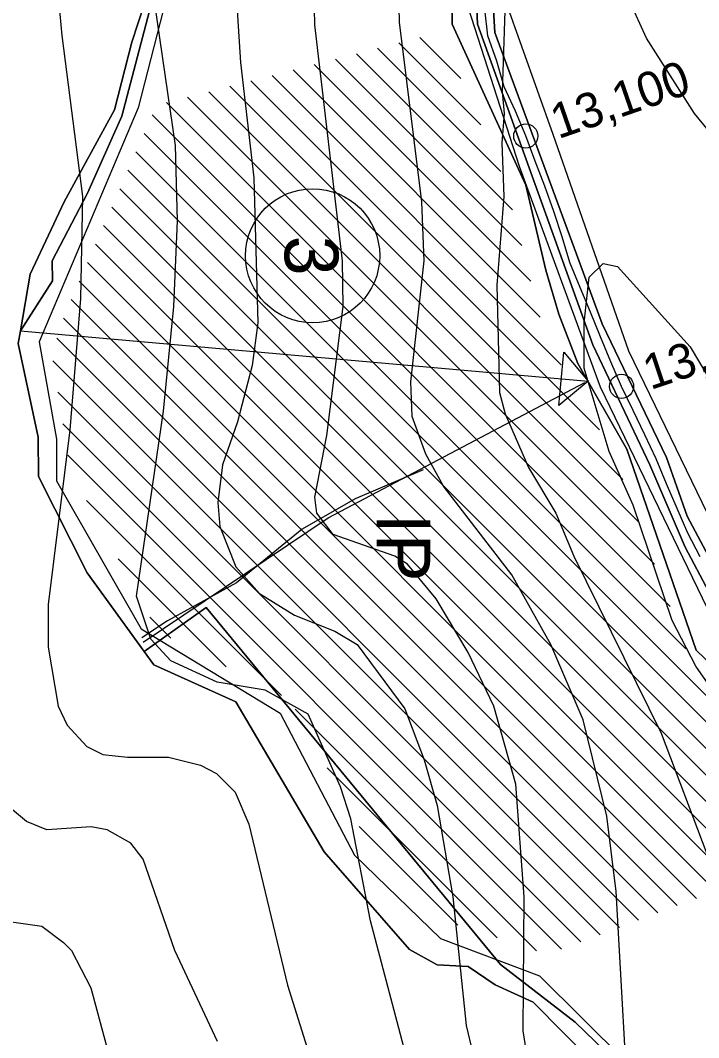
# Model space of a CAD drawing. Extents: x -510989 to -501240, y -1184665 to -1176089.
# Drawn here: x -510240.4 to -509987.5, y -1178334.5 to -1177955.3 of the extents above; entities that cross this region are included whole.
import ezdxf

# ---------------------------------------------------------------- set-up
doc = ezdxf.new("R2010")
doc.units = 0
for name, color, linetype in [('lesni_pozemek', 7, 'Continuous'), ('NAVRH_interakcni_prvky', 7, 'Continuous'), ('NAVRH_revitalizace_toku', 7, 'Continuous'), ('orna_puda', 7, 'Continuous'), ('ostatni_plocha_x_neplodna_puda', 7, 'Continuous'), ('STAV_erozne_ohrozene_plochy', 7, 'Continuous'), ('STAV_odtokove_linie', 7, 'Continuous'), ('STAV_systematicke_odvodneni', 7, 'Continuous'), ('STAV_vyrazne_udolnice', 7, 'Continuous'), ('trasovani_toku', 7, 'Continuous'), ('trvaly_travni_porost', 7, 'Continuous'), ('vodni_plocha_x_vodni_tok_v_koryte_umelem', 7, 'Continuous'), ('vrstevnice_01', 7, 'Continuous'), ('vrstevnice_02', 7, 'Continuous')]:
    doc.layers.add(name, color=color, linetype=linetype)

msp = doc.modelspace()

# ---------------------------------------------------------------- linework, layer by layer
at = {"layer": 'lesni_pozemek'}
msp.add_lwpolyline([(-510189.41, -1177934.52), (-510198.81, -1177963.46), (-510205.37, -1177988.67), (-510224.04, -1178022.91), (-510236.77, -1178049.95), (-510240.38, -1178070.99), (-510241.2, -1178075.75), (-510233.74, -1178110.71), (-510233.66, -1178125.3), (-510215.51, -1178161.2), (-510194.26, -1178190.6), (-510190.68, -1178195.56), (-510160.13, -1178209.33), (-510127.15, -1178265.25), (-510095.33, -1178301.71), (-510084.96, -1178307.4), (-510073.4, -1178308.05), (-510063.41, -1178314.85), (-510049.21, -1178321.31), (-509991.93, -1178379.18)], dxfattribs=at)
msp.add_lwpolyline([(-510187.83, -1177934.64), (-510202.64, -1177991), (-510215.39, -1178019.77), (-510228.62, -1178044.97), (-510228.47, -1178052.46), (-510240.38, -1178070.99), (-510236.77, -1178049.95), (-510224.04, -1178022.91), (-510205.37, -1177988.67), (-510198.81, -1177963.46), (-510189.41, -1177934.52)], close=True, dxfattribs=at)
at = {"layer": 'NAVRH_interakcni_prvky'}
msp.add_lwpolyline([(-510194.66, -1178187.09), (-510125.7, -1178140.77), (-510029.97, -1178090.33)], dxfattribs=at)
at = {"layer": 'NAVRH_revitalizace_toku'}
for points in [[(-510060.1, -1177738.31), (-510046.04, -1177776.27), (-510042.52, -1177800.88), (-510055.18, -1177879.61), (-510059.4, -1177948.51), (-510041.82, -1177997.72), (-510013.7, -1178078.56), (-509968.71, -1178171.36), (-509924.51, -1178222.53), (-509906.94, -1178282.99), (-509903.42, -1178334.31), (-509883.74, -1178387.03), (-509875.3, -1178456.63), (-509874.6, -1178556.46), (-509867.57, -1178669.64)], [(-510079.08, -1177742.53), (-510057.99, -1177785.41), (-510068.53, -1177883.83), (-510073.46, -1177950.62), (-510054.47, -1178009.67), (-510024.24, -1178091.92), (-509980.66, -1178181.91), (-509942.44, -1178221.73), (-509934.15, -1178235.7), (-509920.62, -1178289.39), (-509918.19, -1178331.5), (-509899.91, -1178389.14), (-509890.77, -1178450.3), (-509893.58, -1178526.93), (-509883.74, -1178663.31)]]:
    msp.add_lwpolyline(points, dxfattribs=at)
at = {"layer": 'orna_puda'}
for points in [[(-509986.97, -1177924.63), (-509979.84, -1177959.29), (-509966.64, -1177993.07), (-509958.61, -1178002.56), (-509963.49, -1178019.89), (-509961.34, -1178043.79), (-509958.27, -1178057.57), (-509958.72, -1178072.96), (-509956.26, -1178083.05), (-509933.53, -1178115.39), (-509937.22, -1178120.9), (-509928.78, -1178129.88), (-509922.63, -1178142.75), (-509917.55, -1178147.87), (-509909, -1178165.53), (-509959.6, -1178191.33), (-509969.79, -1178181.42), (-509991.77, -1178140.09), (-509999.48, -1178118.28), (-510023.49, -1178068.48), (-510063.48, -1177959.85), (-510065.05, -1177932.43)], [(-509992.84, -1178367.99), (-510033.53, -1178328.73), (-510061.37, -1178307.23), (-510171.11, -1178174.19), (-510194.26, -1178190.6), (-510215.51, -1178161.2), (-510233.66, -1178125.3), (-510233.74, -1178110.71), (-510241.2, -1178075.75), (-510240.38, -1178070.99), (-510228.47, -1178052.46), (-510228.62, -1178044.97), (-510215.39, -1178019.77), (-510202.64, -1177991), (-510187.83, -1177934.64)], [(-510079.43, -1177947.66), (-510079.36, -1177956.75), (-510051.92, -1178016.68), (-510044.45, -1178048.48), (-510039.57, -1178064.82), (-510032.5, -1178083.21), (-510014.22, -1178115.18), (-509988.47, -1178190.06), (-509953.04, -1178224.13), (-509933.91, -1178266.31), (-509920.86, -1178355.55)]]:
    msp.add_lwpolyline(points, dxfattribs=at)
at = {"layer": 'ostatni_plocha_x_neplodna_puda'}
msp.add_lwpolyline([(-510171.11, -1178174.19), (-510061.37, -1178307.23), (-510033.53, -1178328.73), (-509992.84, -1178367.99), (-509974.29, -1178382.32), (-509974.41, -1178391.9), (-509986.69, -1178390.43), (-509991.93, -1178379.18), (-510049.21, -1178321.31), (-510063.41, -1178314.85), (-510073.4, -1178308.05), (-510084.96, -1178307.4), (-510095.33, -1178301.71), (-510127.15, -1178265.25), (-510160.13, -1178209.33), (-510190.68, -1178195.56), (-510194.26, -1178190.6)], close=True, dxfattribs=at)
at = {"layer": 'STAV_erozne_ohrozene_plochy'}
for p, q in [((-510091.47, -1177961.65), (-510076.17, -1177976.95)), ((-510107.22, -1177965.7), (-510061.31, -1178011.61)), ((-510099.35, -1177963.67), (-510068.74, -1177994.28)), ((-510122.96, -1177969.75), (-510053.48, -1178039.24)), ((-510115.09, -1177967.73), (-510056.9, -1178025.92)), ((-510138.71, -1177973.81), (-510046.63, -1178065.89)), ((-510130.84, -1177971.78), (-510050.05, -1178052.57)), ((-510154.45, -1177977.86), (-510024.43, -1178107.89)), ((-510146.58, -1177975.84), (-510038.72, -1178083.7)), ((-510170.2, -1177981.92), (-510009.89, -1178142.23)), ((-510162.33, -1177979.89), (-510015.77, -1178126.45)), ((-510185.94, -1177985.97), (-509998.13, -1178173.79)), ((-510178.07, -1177983.94), (-510004.01, -1178158.01)), ((-510191.28, -1177990.53), (-509992.25, -1178189.57)), ((-510194.3, -1177997.42), (-509952.67, -1178239.04)), ((-510197.31, -1178004.3), (-509941.41, -1178260.2)), ((-510200.33, -1178011.18), (-509945.17, -1178266.34)), ((-510203.35, -1178018.06), (-509952.36, -1178269.05)), ((-510206.37, -1178024.95), (-509959.55, -1178271.76)), ((-510209.38, -1178031.83), (-509966.74, -1178274.47)), ((-510212.4, -1178038.71), (-509973.93, -1178277.18)), ((-510215.42, -1178045.59), (-509981.12, -1178279.89)), ((-510218.43, -1178052.48), (-509988.31, -1178282.6)), ((-510221.45, -1178059.36), (-509995.5, -1178285.31)), ((-510224.35, -1178066.36), (-510002.69, -1178288.02)), ((-510226.77, -1178073.83), (-510009.88, -1178290.73)), ((-510228.3, -1178082.21), (-510017.07, -1178293.44)), ((-510226.45, -1178093.95), (-510024.26, -1178296.14)), ((-510224.6, -1178105.7), (-510031.45, -1178298.85)), ((-510222.75, -1178117.45), (-510038.64, -1178301.56)), ((-510215.75, -1178134.35), (-510143.07, -1178207.03)), ((-510203.95, -1178156.05), (-510163.7, -1178196.3)), ((-510192.15, -1178177.76), (-510184.33, -1178185.57)), ((-510138.01, -1178212.1), (-510047.94, -1178302.16)), ((-510126.02, -1178233.98), (-510062.63, -1178297.38)), ((-510114.03, -1178255.87), (-510077.32, -1178292.59))]:
    msp.add_line(p, q, dxfattribs=at)
at = {"layer": 'STAV_odtokove_linie'}
msp.add_line((-510240.38, -1178070.99), (-510028.74, -1178089.79), dxfattribs=at)
msp.add_lwpolyline([(-510037.81, -1178078.94), (-510028.74, -1178089.79), (-510039.59, -1178098.86)], close=True, dxfattribs=at)
msp.add_circle((-510131.43, -1178043.05), 25, dxfattribs=at)
at = {"layer": 'STAV_systematicke_odvodneni'}
for p, q in [((-510184.72, -1177941.97), (-510196.48, -1177987.96)), ((-510196.48, -1177987.96), (-510233.36, -1178075.12)), ((-510233.36, -1178075.12), (-510226.95, -1178111.48)), ((-510226.95, -1178111.48), (-510226.95, -1178126.99)), ((-510226.95, -1178126.99), (-510195.41, -1178182.07)), ((-510195.41, -1178182.07), (-510143.56, -1178213.62)), ((-510143.56, -1178213.62), (-510115.77, -1178266.56)), ((-510115.77, -1178266.56), (-510083.7, -1178297.58)), ((-510083.7, -1178297.58), (-510046.81, -1178311.48)), ((-510046.81, -1178311.48), (-509988.02, -1178369.77))]:
    msp.add_line(p, q, dxfattribs=at)
at = {"layer": 'STAV_vyrazne_udolnice'}
msp.add_lwpolyline([(-510090.27, -1178122.86), (-510115.59, -1178133.7), (-510135.29, -1178144.95), (-510159.8, -1178165.04), (-510185.52, -1178179.1), (-510195.17, -1178185.53)], dxfattribs=at)
at = {"layer": 'trasovani_toku'}
for p, q in [((-510066.12, -1177961.08), (-510067.19, -1177951.14)), ((-510062.73, -1177970.49), (-510066.12, -1177961.08)), ((-510060, -1177980.11), (-510062.73, -1177970.49)), ((-510055.74, -1177989.15), (-510060, -1177980.11)), ((-510051.95, -1177998.41), (-510055.74, -1177989.15)), ((-510048.43, -1178007.77), (-510051.95, -1177998.41)), ((-510044.83, -1178017.1), (-510048.43, -1178007.77)), ((-510041.54, -1178026.54), (-510044.83, -1178017.1)), ((-510038.43, -1178036.04), (-510041.54, -1178026.54)), ((-510035.53, -1178045.61), (-510038.43, -1178036.04)), ((-510031.72, -1178054.86), (-510035.53, -1178045.61)), ((-510027.77, -1178064.05), (-510031.72, -1178054.86)), ((-510024.05, -1178073.33), (-510027.77, -1178064.05)), ((-510020.21, -1178082.56), (-510024.05, -1178073.33)), ((-510016.25, -1178091.75), (-510020.21, -1178082.56)), ((-510011.95, -1178100.78), (-510016.25, -1178091.75)), ((-510007.61, -1178109.78), (-510011.95, -1178100.78)), ((-510003.28, -1178118.8), (-510007.61, -1178109.78)), ((-509999.51, -1178128.06), (-510003.28, -1178118.8)), ((-509995.53, -1178137.23), (-509999.51, -1178128.06)), ((-509991.57, -1178146.42), (-509995.53, -1178137.23)), ((-509986.95, -1178155.29), (-509991.57, -1178146.42))]:
    msp.add_line(p, q, dxfattribs=at)
for centre in [(-510051.95, -1177998.41), (-510016.25, -1178091.75)]:
    msp.add_circle(centre, 4.5, dxfattribs=at)
at = {"layer": 'trvaly_travni_porost'}
for points in [[(-510070.88, -1177937.17), (-510070.02, -1177956.7), (-510026.99, -1178076.31), (-510005.75, -1178120.95), (-509992.58, -1178151.71), (-509974.89, -1178184.95), (-509954.9, -1178204.95), (-509939.87, -1178216.72), (-509930.25, -1178235.71), (-509917.34, -1178285.83), (-509915.23, -1178335.99)], [(-509920.86, -1178355.55), (-509933.91, -1178266.31), (-509953.04, -1178224.13), (-509988.47, -1178190.06), (-510014.22, -1178115.18), (-510032.5, -1178083.21), (-510039.57, -1178064.82), (-510044.45, -1178048.48), (-510051.92, -1178016.68), (-510079.36, -1177956.75), (-510079.43, -1177947.66)]]:
    msp.add_lwpolyline(points, dxfattribs=at)
at = {"layer": 'vodni_plocha_x_vodni_tok_v_koryte_umelem'}
for points in [[(-510065.05, -1177932.43), (-510063.48, -1177959.85), (-510023.49, -1178068.48), (-509999.48, -1178118.28), (-509991.77, -1178140.09), (-509969.79, -1178181.42), (-509959.6, -1178191.33), (-509947.55, -1178203.07), (-509947.15, -1178203.4), (-509934.53, -1178214.01), (-509924.24, -1178235.26), (-509911.5, -1178286.83), (-509909.49, -1178335.01)], [(-509915.23, -1178335.99), (-509917.34, -1178285.83), (-509930.25, -1178235.71), (-509939.87, -1178216.72), (-509954.9, -1178204.95), (-509974.89, -1178184.95), (-509992.58, -1178151.71), (-510005.75, -1178120.95), (-510026.99, -1178076.31), (-510070.02, -1177956.7), (-510070.88, -1177937.17)]]:
    msp.add_lwpolyline(points, dxfattribs=at)
at = {"layer": 'vrstevnice_01'}
for points in [[(-510056.41, -1177850), (-510060.81, -1177982), (-510060, -1177990), (-510060.91, -1178001), (-510060.19, -1178021), (-510062.69, -1178054), (-510061.81, -1178094), (-510059.69, -1178102), (-510050.91, -1178122), (-510040.69, -1178139), (-510034, -1178155), (-510001.5, -1178221), (-509984.5, -1178266), (-509979.09, -1178288), (-509977, -1178322), (-509980.69, -1178389)], [(-510126.19, -1178110), (-510120, -1178062), (-510120.31, -1178045), (-510130.59, -1177957), (-510131.09, -1177933)], [(-510166.91, -1178336), (-510182.81, -1178302), (-510194.59, -1178268), (-510199.19, -1178262), (-510208, -1178257), (-510214, -1178256), (-510230.59, -1178257), (-510238.19, -1178254), (-510244.09, -1178249), (-510251.59, -1178232), (-510254.5, -1178207), (-510255.91, -1178159), (-510255.41, -1178132), (-510247.41, -1178065), (-510246.41, -1178037), (-510247.31, -1178019), (-510253.09, -1177986), (-510262.41, -1177945)], [(-509862.41, -1178214), (-509909, -1178151), (-509927.69, -1178097), (-509930.19, -1178077), (-509928.41, -1178056), (-509922.5, -1178038), (-509922.81, -1178033), (-509933.5, -1178031), (-509946.31, -1178032), (-509960.69, -1178021), (-509973.41, -1178009), (-509989, -1177990), (-510006.91, -1177962), (-510013.31, -1177948)], [(-510096.91, -1178340), (-510109.81, -1178291), (-510117.19, -1178253), (-510121, -1178241), (-510133.09, -1178214), (-510149.09, -1178205), (-510167.09, -1178202), (-510184.31, -1178194), (-510191.81, -1178186), (-510197.09, -1178170), (-510187.09, -1178101), (-510183.19, -1178062), (-510181.81, -1178030), (-510182.59, -1178002), (-510190.31, -1177949)], [(-510048.81, -1178358), (-510052.91, -1178332), (-510052.59, -1178282), (-510055.69, -1178240), (-510063.81, -1178211), (-510073.5, -1178191), (-510085.41, -1178171), (-510096.09, -1178158), (-510100.81, -1178155), (-510123.81, -1178147), (-510129.91, -1178139), (-510130.59, -1178133), (-510126.19, -1178110)]]:
    msp.add_lwpolyline(points, dxfattribs=at)
at = {"layer": 'vrstevnice_02'}
for points in [[(-510042.59, -1178188), (-510057.19, -1178162), (-510082.69, -1178129), (-510089.19, -1178117), (-510094.31, -1178103), (-510094.81, -1178090), (-510089.81, -1178045), (-510090.69, -1178023), (-510099.09, -1177956), (-510099.69, -1177928)], [(-510227.59, -1177933), (-510225, -1177961), (-510217.31, -1178021), (-510218, -1178059), (-510222, -1178108), (-510230.09, -1178173), (-510230.09, -1178189), (-510226.31, -1178211), (-510223, -1178218), (-510215.59, -1178226), (-510209.69, -1178229), (-510200.41, -1178230), (-510185.19, -1178230), (-510173.19, -1178233), (-510167.31, -1178236), (-510160.31, -1178243), (-510155.19, -1178255), (-510140.81, -1178315), (-510127.59, -1178357)], [(-510160.41, -1177938), (-510158.31, -1177971), (-510153.41, -1178014), (-510151.91, -1178068), (-510154, -1178084), (-510159.5, -1178105), (-510165.09, -1178121), (-510166.81, -1178135), (-510166, -1178144), (-510160.09, -1178159), (-510151.31, -1178169), (-510138.19, -1178177), (-510123.19, -1178183), (-510114.81, -1178188), (-510097.09, -1178212), (-510089.81, -1178231), (-510085, -1178248), (-510079.19, -1178282), (-510074.19, -1178330), (-510071.81, -1178340), (-510062.5, -1178411)], [(-510293.81, -1177941), (-510293.09, -1177957), (-510288.09, -1177997), (-510288.19, -1178028), (-510293.09, -1178055), (-510298.91, -1178109), (-510298.69, -1178167), (-510281.91, -1178239), (-510274.69, -1178262), (-510262.41, -1178283), (-510253.59, -1178290), (-510232.41, -1178293), (-510224.31, -1178299), (-510221.31, -1178302), (-510214.19, -1178316), (-510198, -1178376)], [(-509955.81, -1178401), (-509948.69, -1178326), (-509950.5, -1178283), (-509952.5, -1178267), (-509957.09, -1178249), (-509968.31, -1178225), (-509988.5, -1178196), (-509997.41, -1178179), (-510011.91, -1178136), (-510020.81, -1178116), (-510030.19, -1178085), (-510030.19, -1178068), (-510028.31, -1178051), (-510023.09, -1178046), (-510017.81, -1178047), (-509990.69, -1178077), (-509967.41, -1178116), (-509943.91, -1178151), (-509910.19, -1178192), (-509893.5, -1178209), (-509874.69, -1178225), (-509869.19, -1178233), (-509862.69, -1178251), (-509844.09, -1178276)], [(-510012.91, -1178375), (-510018.31, -1178280), (-510021.69, -1178252), (-510030.59, -1178216), (-510042.59, -1178188)]]:
    msp.add_lwpolyline(points, dxfattribs=at)

# ---------------------------------------------------------------- texts
at = {"layer": 'NAVRH_interakcni_prvky'}
msp.add_text('IP', height=20, rotation=270, dxfattribs=at).set_placement((-510107.58, -1178139.22))
at = {"layer": 'STAV_odtokove_linie'}
msp.add_text('3', height=20, rotation=270, dxfattribs=at).set_placement((-510141.85, -1178035.58))
at = {"layer": 'trasovani_toku'}
for s, rotation, p in [('13,100', 19.1411, (-510039.85, -1177999.64)), ('13,000', 18.4422, (-510005.49, -1178093.14))]:
    msp.add_text(s, height=13, rotation=rotation, dxfattribs=at).set_placement(p)

doc.saveas('drawing.dxf')
